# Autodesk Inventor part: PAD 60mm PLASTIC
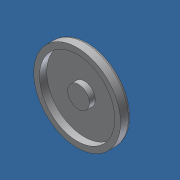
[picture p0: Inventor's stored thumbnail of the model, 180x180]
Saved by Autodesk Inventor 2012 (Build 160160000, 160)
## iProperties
Created: 2007-03
Part Number: PAD 60mm PLASTIC
Document SubType Name: Modeling
Designer: Andy Moles
Material: ABS Plastic
Density: 1.06 g/cm^3
Mass: 25.313 g
Surface Area: 86.7013 cm^2
Volume: 23.8801 cm^3
Author: Andy Moles
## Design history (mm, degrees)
sketch "Sketch1"
  geometry: L1 (0, 0)-(30, 0); L2 (30, 0)-(30, 5.404); L3 (0, 0)-(0, 18); L4 (6.633, 18)-(11.416, 18); L5 (29.077, 7.09)-(12.492, 17.685); L6 (0, 0)-(0, 7); A1 r 7.5 centre (0, 14.5) between (0, 7) and (6.633, 18); A2 r 2 centre (11.416, 16) between (12.492, 17.685) and (11.416, 18); A3 r 2 centre (28, 5.404) between (30, 5.404) and (29.077, 7.09); 2 further points
  constraints: 12 end point, 6 point on circle, 6 point on line, 4 tangent, 3 centre point, 2 perpendicular, 1 collinear, 1 equal radius, 1 horizontal, 1 parallel
  dimensions: "d0" = 30 distance of L1.start L1.end; "d1" = 6.5 distance of L1.end point (30, 6.5); "d2" = 18 distance of L1.start L3.end; "d3" = 15 diameter of A1; "d4" = 3.5 distance of A1.centre L3.end; "d5" = 12 horizontal distance of point (12, 18) L1.start; "d6" = 2 radius of A2; "d14" = 18 distance between parallel lines of L4 L1
revolve "Revolution1" sketch "Sketch1" stored, may be unused: angle "d7" = 90 deg
sketch "Sketch2"
  geometry: C1 r 30 at (0, 0) reference; C2 r 7.5 at (0, 0)
  constraints: 1 centre point, 1 coincident
  dimensions: "d8" = 15 diameter of C2
extrude "Extrusion1" cut sketch "Sketch2" distance "d9" = 1; taper "d10" = 0 deg
sketch "Sketch3"
  geometry: C1 r 7.5 at (0, 0) reference; C2 r 30 at (0, 0) reference; C3 r 26 at (0, 0)
  constraints: 1 centre point, 1 coincident
  dimensions: "d11" = 4 radial gap between concentric circles of C2 C3
extrude "Extrusion2" cut sketch "Sketch3" distance "d12" = 5; taper "d13" = 0 deg
body "Solid1"
